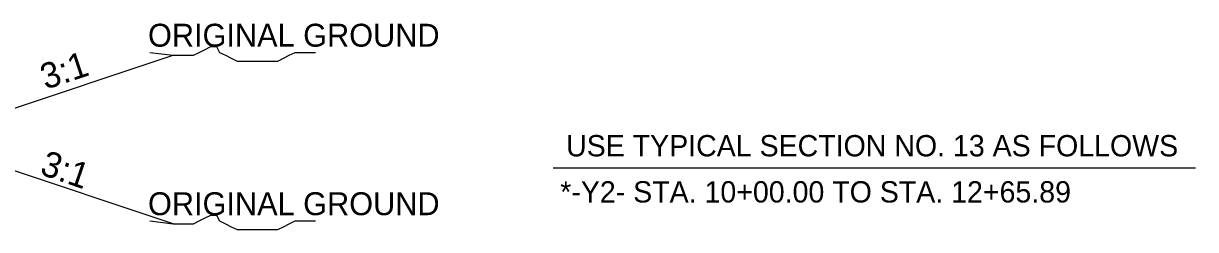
# Model space of a CAD drawing. Extents: x 958711 to 962106, y 831169 to 840840.
# Drawn here: x 961519.5 to 961877, y 835019.8 to 835082.8 of the extents above; entities that cross this region are included whole.
import ezdxf

# ---------------------------------------------------------------- set-up
doc = ezdxf.new("R2010")
doc.units = 0
for name, color, linetype in [('Old_Level_1', 7, 'Continuous'), ('Old_Level_21', 7, 'Continuous'), ('Old_Level_3', 7, 'Continuous')]:
    doc.layers.add(name, color=color, linetype=linetype)

msp = doc.modelspace()

# ---------------------------------------------------------------- linework, layer by layer
at = {"layer": 'Old_Level_1'}
for p, q in [((961487.93, 835047.29), (961565.11, 835073.02)), ((961565.11, 835021.56), (961487.93, 835047.29)), ((961681.07, 835038.63), (961877.01, 835038.63))]:
    msp.add_line(p, q, dxfattribs=at)
at = {"layer": 'Old_Level_21'}
for points in [[(961558.02, 835073.9), (961565.11, 835073.02), (961566.89, 835073.02), (961569.55, 835073.02), (961571.33, 835073.02), (961573.1, 835073.9), (961574.87, 835074.8), (961576.64, 835075.68), (961578.42, 835075.68), (961579.32, 835073.9), (961581.08, 835073.02), (961582.86, 835072.13), (961584.63, 835071.25), (961586.4, 835071.25), (961588.17, 835071.25), (961589.95, 835071.25), (961591.72, 835071.25), (961593.5, 835071.25), (961595.27, 835071.25), (961597.04, 835071.25), (961598.81, 835072.13), (961600.58, 835073.02), (961602.35, 835073.9), (961605.03, 835073.9), (961606.79, 835073.9), (961608.57, 835073.9)], [(961558.02, 835022.44), (961565.11, 835021.56), (961566.89, 835021.56), (961569.55, 835021.56), (961571.33, 835021.56), (961573.1, 835022.44), (961574.87, 835023.34), (961576.64, 835024.22), (961578.42, 835024.22), (961579.32, 835022.44), (961581.08, 835021.56), (961582.86, 835020.66), (961584.63, 835019.79), (961586.4, 835019.79), (961588.17, 835019.79), (961589.95, 835019.79), (961591.72, 835019.79), (961593.5, 835019.79), (961595.27, 835019.79), (961597.04, 835019.79), (961598.81, 835020.66), (961600.58, 835021.56), (961602.35, 835022.44), (961605.03, 835022.44), (961606.79, 835022.44), (961608.57, 835022.44)]]:
    msp.add_lwpolyline(points, dxfattribs=at)

# ---------------------------------------------------------------- texts
at = {"layer": 'Old_Level_1'}
for s, p in [('USE TYPICAL SECTION NO. 13 AS FOLLOWS', (961685.01, 835042.15)), ('*-Y2- STA. 10+00.00 TO STA. 12+65.89', (961683.22, 835028.06))]:
    msp.add_text(s, height=6.5088, dxfattribs=at).set_placement(p)
at = {"layer": 'Old_Level_21'}
for p in [(961557.48, 835075.65), (961557.48, 835024.19)]:
    msp.add_text('ORIGINAL GROUND', height=7, dxfattribs=at).set_placement(p)
at = {"layer": 'Old_Level_3'}
for rotation, p in [(18.4348, (961526.23, 835062.47)), (341.0454, (961524.17, 835036.79))]:
    msp.add_text('3:1', height=7.801, rotation=rotation, dxfattribs=at).set_placement(p)

doc.saveas('drawing.dxf')
